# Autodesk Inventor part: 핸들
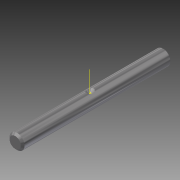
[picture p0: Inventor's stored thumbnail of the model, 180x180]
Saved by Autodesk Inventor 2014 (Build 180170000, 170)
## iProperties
Created: 2019-04
Part Number: 핸들
Material: 스테인리스강
Document SubType Name: Modeling
Designer: mduedu
Density: 1 g/cm^3
Appearance: 반광택
Author: mduedu
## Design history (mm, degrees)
sketch "스케치1"
  geometry: C1 r 4 at (0, 0); 1 further point
  constraints: 1 centre point, 1 coincident
  dimensions: "d0" = 8 diameter of C1
extrude "돌출1" new body sketch "스케치1" stored distance "d1" = 80; taper "d2" = 0 deg
chamfer "모따기1" distance "d3" = 1; stored, may be unused: second distance "d4" = 2, angle "d5" = 45 deg
sketch "스케치2"
  geometry: L1 (-39, 4)-(39, 4) reference; L2 (0, 4)-(0, 2); L3 (0, 2)-(2, 4); L4 (0, 4)-(2, 4); 1 further point
  constraints: 6 end point, 2 perpendicular, 1 midpoint, 1 point on line
  dimensions: "d6" = 4 diameter of L3.end L2; "d8" = 45 deg angle of L3 L2
revolve "회전1" sketch "스케치2" stored, may be unused: angle "d10" = 90 deg
node "작업점1"
  node "작업축1"
  node "작업 평면1"
workpoint "Work Point2"
  workaxis "Work Axis2"
node "솔리드1"
